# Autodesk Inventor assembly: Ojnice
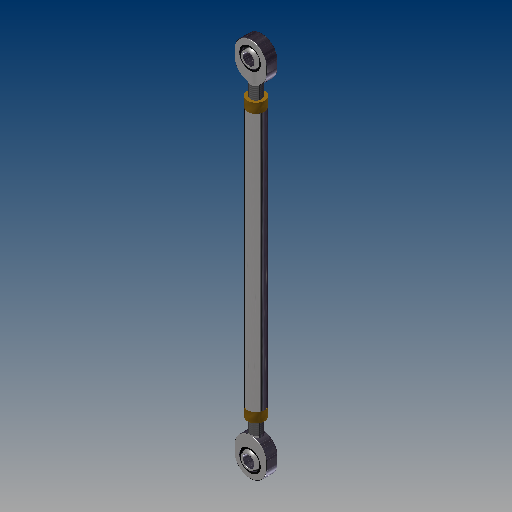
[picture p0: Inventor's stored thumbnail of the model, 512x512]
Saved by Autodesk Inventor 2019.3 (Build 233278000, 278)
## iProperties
Created: 2019-01
Part Number: Ojnice
Material: Všeobecné
Document SubType Name: Assembly
Designer: B-hon
Author: B-hon
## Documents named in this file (3)
- C:\Users\B-hon\OneDrive\Plocha\Bakalářka22\Ojnice\Ojnice.iam
- C:\Users\B-hon\OneDrive\Plocha\Bakalářka22\Ojnice\Ojniční tyč.iam
- C:\Users\B-hon\OneDrive\Plocha\Bakalářka22\Ojnice\Hlavice.iam
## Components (3 placed, 2 different names)
1. Ojniční tyč:1 [sub-assembly] — Vložit:1, Vložit:2
2. Hlavice:1 [sub-assembly] — Vložit:1, Úhel:1
3. Hlavice:2 [sub-assembly] — Vložit:2, Úhel:1
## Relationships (3: Insert 2, Angle 1)
- Vložit:1 [Insert]: Ojniční tyč:1 ↔ Hlavice:1
- Vložit:2 [Insert]: Ojniční tyč:1 ↔ Hlavice:2
- Úhel:1 [Angle]: Hlavice:1 ↔ Hlavice:2
